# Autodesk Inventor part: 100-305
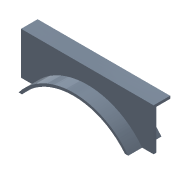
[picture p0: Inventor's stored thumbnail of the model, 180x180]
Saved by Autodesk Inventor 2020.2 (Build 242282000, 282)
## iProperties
Created: 2011-01
Part Number: 100-305
Document SubType Name: Modeling
Designer: F.Stasiak
Density: 1 g/cm^3
Material: Ogólny
Appearance: Stalowoniebieska
Company: Fabian Stasiak CAD Consulting
Manager: www.cadconsulting.pl
Author: F.Stasiak
Subject: Zbiór ćwiczeń. Autodesk Inventor 2020. Kurs podstawowy
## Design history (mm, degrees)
sketch "Szkic1"
  geometry: L1 (-200, -25)-(200, -25); L2 (200, -25)-(200, 25); L3 (200, 25)-(-200, 25); L4 (-200, 25)-(-200, -25); 3 further points
  constraints: 8 end point, 2 midpoint, 2 parallel, 1 horizontal, 1 horizontal alignment, 1 perpendicular, 1 vertical alignment
  dimensions: "d0" = 400 distance of L3.end L2.end; "d1" = 50 distance of L2.end L1.end
extrude "Wyciągnięcie proste1" new body sketch "Szkic1" distance "d2" = 8; taper "d3" = 0 deg
sketch "Szkic2"
  geometry: L1 (-200, -25)-(-200, 25) reference; L2 (200, -25)-(-200, -25) reference; L3 (200, 25)-(200, -25) reference; L4 (-200, 25)-(200, 25) reference; L5 (200, -17)-(-200, -17); 1 further point
  constraints: 2 end point, 2 point on line, 1 parallel
  dimensions: "d4" = 8 distance between parallel lines of L5 L2 (= d2)
extrude "Wyciągnięcie proste2" join sketch "Szkic2" distance "d5" = 120; taper "d6" = 0 deg
sketch "Szkic5"
  geometry: C1 r 200 at (200, 246) reference; 1 further point
extrude "Wyciągnięcie proste5" cut sketch "Szkic5" extent not by distance; stored distance "d13" = 0; taper "d14" = 0 deg
sketch "Szkic6"
  geometry: L1 (44.681, 120)-(0, 120) reference; L2 (400, 120)-(355.319, 120) reference; A1 r 200 centre (200, 246) between (44.681, 120) and (355.319, 120) reference; A2 r 208 centre (200, 246) between (34.507, 120) and (365.493, 120); 1 further point
  constraints: 2 point on circle, 2 point on line, 1 centre point
  dimensions: "d15" = 8 radial gap between concentric circles of A1 A2 (= d2)
extrude "Wyciągnięcie proste6" join sketch "Szkic6" stored distance "d16" = 100; taper "d17" = 0 deg
node "Bryła1"
node "Pętla rzutowana1"
node "Odniesienie2"
